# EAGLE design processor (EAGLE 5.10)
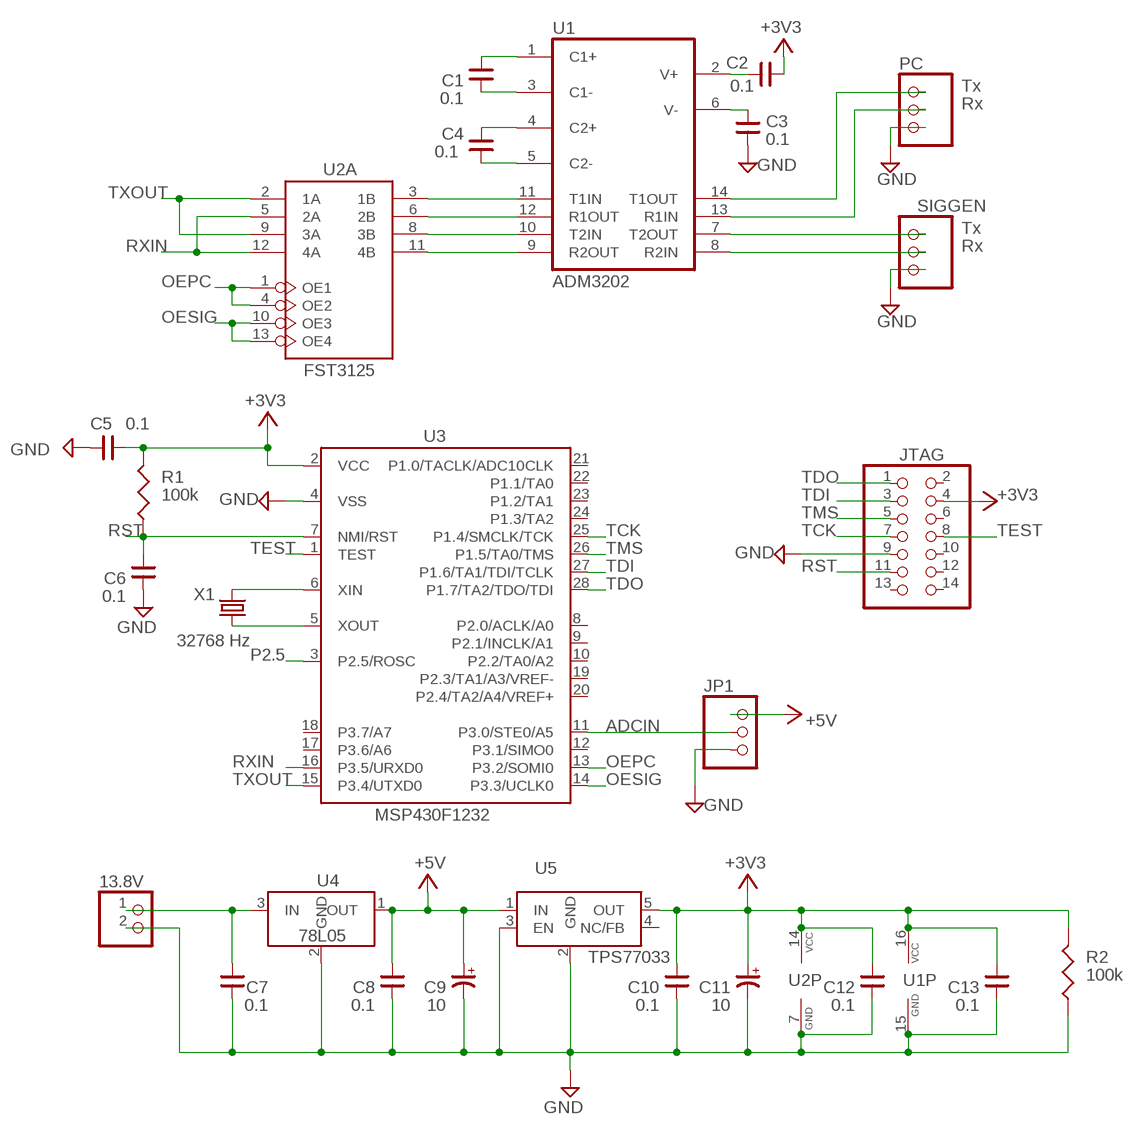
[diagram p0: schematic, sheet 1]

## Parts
13.8V  HIROSE-1X2C  [HIROSE-1X2]
C1  0.1  CAP-NPDC  [805C]
C2  0.1  CAP-NPDC  [805C]
C3  0.1  CAP-NPDC  [805C]
C4  0.1  CAP-NPDC  [805C]
C5  0.1  CAP-NPDC  [805C]
C6  0.1  CAP-NPDC  [805C]
C7  0.1  CAP-NPDC  [805C]
C8  0.1  CAP-NPDC  [805C]
C9  10  CAP-PH  [BC45196H-B]
C10  0.1  CAP-NPDC  [805C]
C11  10  CAP-PH  [BC45196H-B]
C12  0.1  CAP-NPDC  [805C]
C13  0.1  CAP-NPDC  [805C]
JP1  PINHD-1X3A  [1X03A]
JTAG  PINHD-2X7  [2X7]
PC  pc  PINHD-1X3A  [1X03A]
R1  100k  RESISTORC  [805C]
R2  100k  RESISTORC  [805C]
SIGGEN  PINHD-1X3A  [1X03A]
U1  ADM3202  ADM3202A  [SOIC16T]
U2  FST3125  [SO14]
U3  MSP430F1232  [SO-28(DW)]
U4  78L05  VOLTAGE-REGULATOR-FIXEDC  [SOT89]
U5  TPS77033  VOLTAGE-REGULATOR-3  [SOT23-5]
X1  32768 Hz  XTAL  [WATCH-CRYSTAL]

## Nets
13.8V: 13.8V.1 C7.2 U4.3(IN)
+3V3: C2.1 C5.2 C10.2 C11.+ C12.2 C13.2 JTAG.4 R1.2 R2.2 U1.16(VCC) U2.14(P:VCC) U3.2(VCC) U5.5(OUT)
+5V: C8.2 C9.+ JP1.1 U4.1(OUT) U5.1(IN)
ADCIN: JP1.2 U3.11(P3.0/STE0/A5)
GND: 13.8V.2 C3.1 C5.1 C6.1 C7.1 C8.1 C9.- C10.1 C11.- C12.1 C13.1 JP1.3 JTAG.9 PC.1 R2.1 SIGGEN.1 U1.15(GND) U2.7(P:GND) U3.4(VSS) U4.2(GND) U5.2(GND) U5.3(EN)
N$2: U1.11(T1IN) U2.3(A:1B)
N$3: U3.6(XIN) X1.P$2
N$4: U1.12(R1OUT) U2.6(A:2B)
N$8: U3.5(XOUT) X1.P$1
N$9: C2.2 U1.2(V+)
N$10: C1.2 U1.1(C1+)
N$11: C1.1 U1.3(C1-)
N$12: C4.1 U1.4(C2+)
N$13: C4.2 U1.5(C2-)
N$14: C3.2 U1.6(V-)
OEPC: U2.1(A:OE1) U2.4(A:OE2) U3.13(P3.2/SOMI0)
OESIG: U2.10(A:OE3) U2.13(A:OE4) U3.14(P3.3/UCLK0)
P2.5: U3.3(P2.5/ROSC)
PRX: PC.2 U1.13(R1IN)
PTX: PC.3 U1.14(T1OUT)
R2OUT: U1.9(R2OUT) U2.11(A:4B)
RST: C6.2 JTAG.11 R1.1 U3.7(NMI/RST)
RXIN: U2.5(A:2A) U2.12(A:4A) U3.16(P3.5/URXD0)
SRX: SIGGEN.2 U1.8(R2IN)
STX: SIGGEN.3 U1.7(T2OUT)
T2IN: U1.10(T2IN) U2.8(A:3B)
TCK: JTAG.7 U3.25(P1.4/SMCLK/TCK)
TDI: JTAG.3 U3.27(P1.6/TA1/TDI/TCLK)
TDO: JTAG.1 U3.28(P1.7/TA2/TDO/TDI)
TEST: JTAG.8 U3.1(TEST)
TMS: JTAG.5 U3.26(P1.5/TA0/TMS)
TXOUT: U2.2(A:1A) U2.9(A:3A) U3.15(P3.4/UTXD0)
Unconnected: JTAG.2 JTAG.6 JTAG.10 JTAG.12 JTAG.13 JTAG.14 U3.8(P2.0/ACLK/A0) U3.9(P2.1/INCLK/A1) U3.10(P2.2/TA0/A2) U3.12(P3.1/SIMO0) U3.17(P3.6/A6) U3.18(P3.7/A7) U3.19(P2.3/TA1/A3/VREF-) U3.20(P2.4/TA2/A4/VREF+) U3.21(P1.0/TACLK/ADC10CLK) U3.22(P1.1/TA0) U3.23(P1.2/TA1) U3.24(P1.3/TA2) U5.4(NC/FB)

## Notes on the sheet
- Tx
- Rx
- TXOUT
- Tx
- RXIN | Rx
- OEPC
- OESIG
- TDO
- TDI
- TMS
- RST | TCK | TCK | TEST
- TEST | TMS
- TDI | RST
- TDO
- P2.5
- ADCIN
- RXIN | OEPC
- TXOUT | OESIG

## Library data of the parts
13.8V = agarConn:HIROSE-1X2: Hirose DF3-2S-2C, 2 mm pin spacing.
C1-C8 C10 C12 C13 = agar:CAP-NP: Non-polarized capacitor
C9 C11 = agar:CAP-P: Polarized capacitor
JP1 PC SIGGEN = agarConn:PINHD-1X3
JTAG = agarConn:PINHD-2X7
R1 R2 = agar:RESISTOR
U1 = agarDigital:ADM3202: 3.3V dual RS-232 line driver/receiver
U2 = agarDigital:FST3125: 4-Bit Bus Switch
U3 = agarDigital:MSP430F1232
U4 = agarVoltageReg:VOLTAGE-REGULATOR-FIXED: 78xx, 78Lxx. No tRestrict, bRestrict
U5 = agarVoltageReg:VOLTAGE-REGULATOR-3: Voltage regulator with enable. ~ TPS770XX
X1 = agarDigital:XTAL: CRYSTAL

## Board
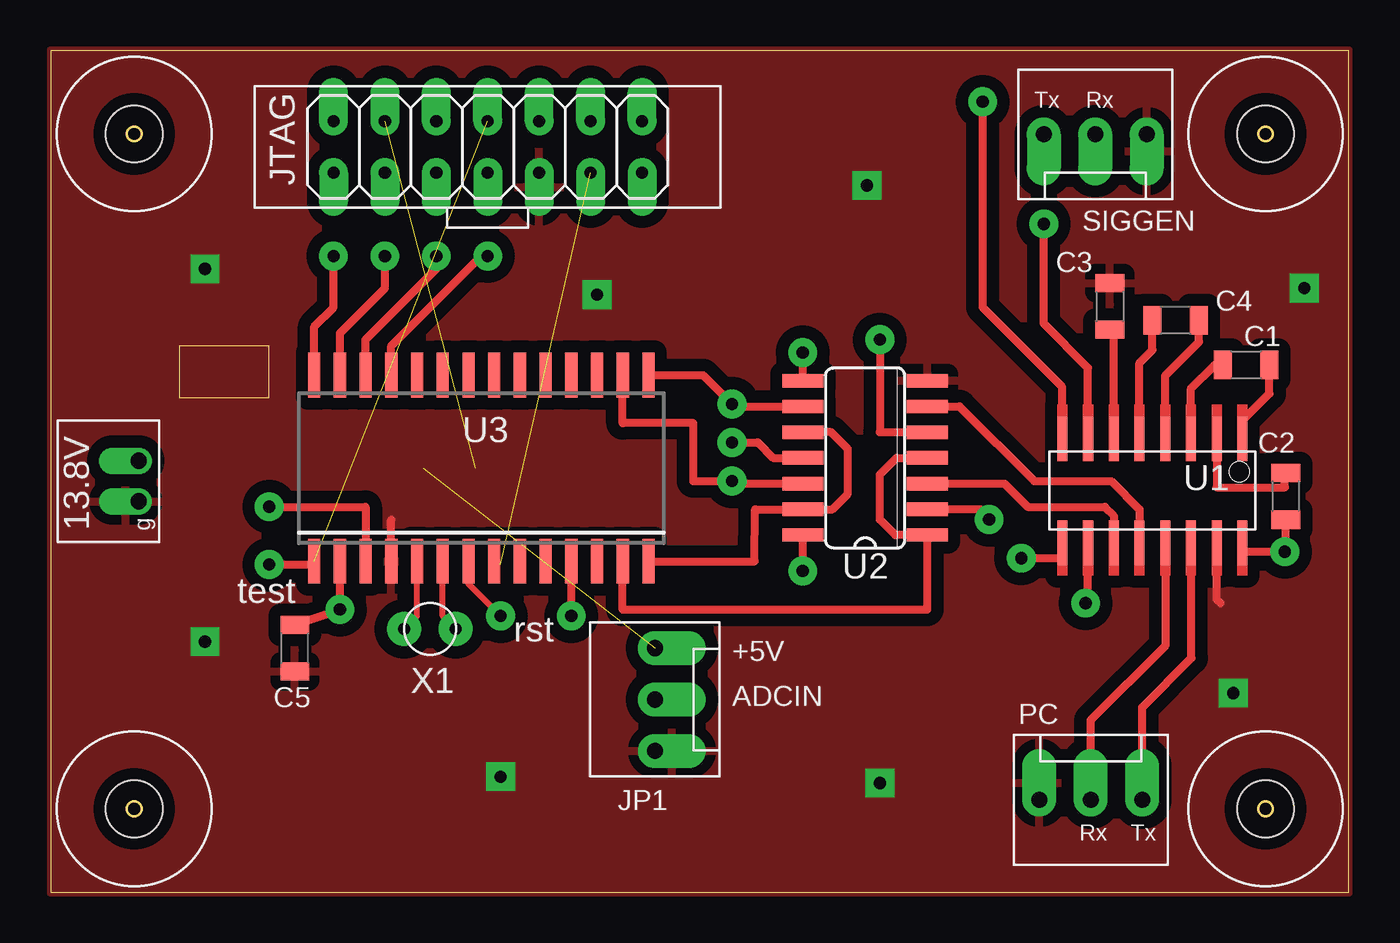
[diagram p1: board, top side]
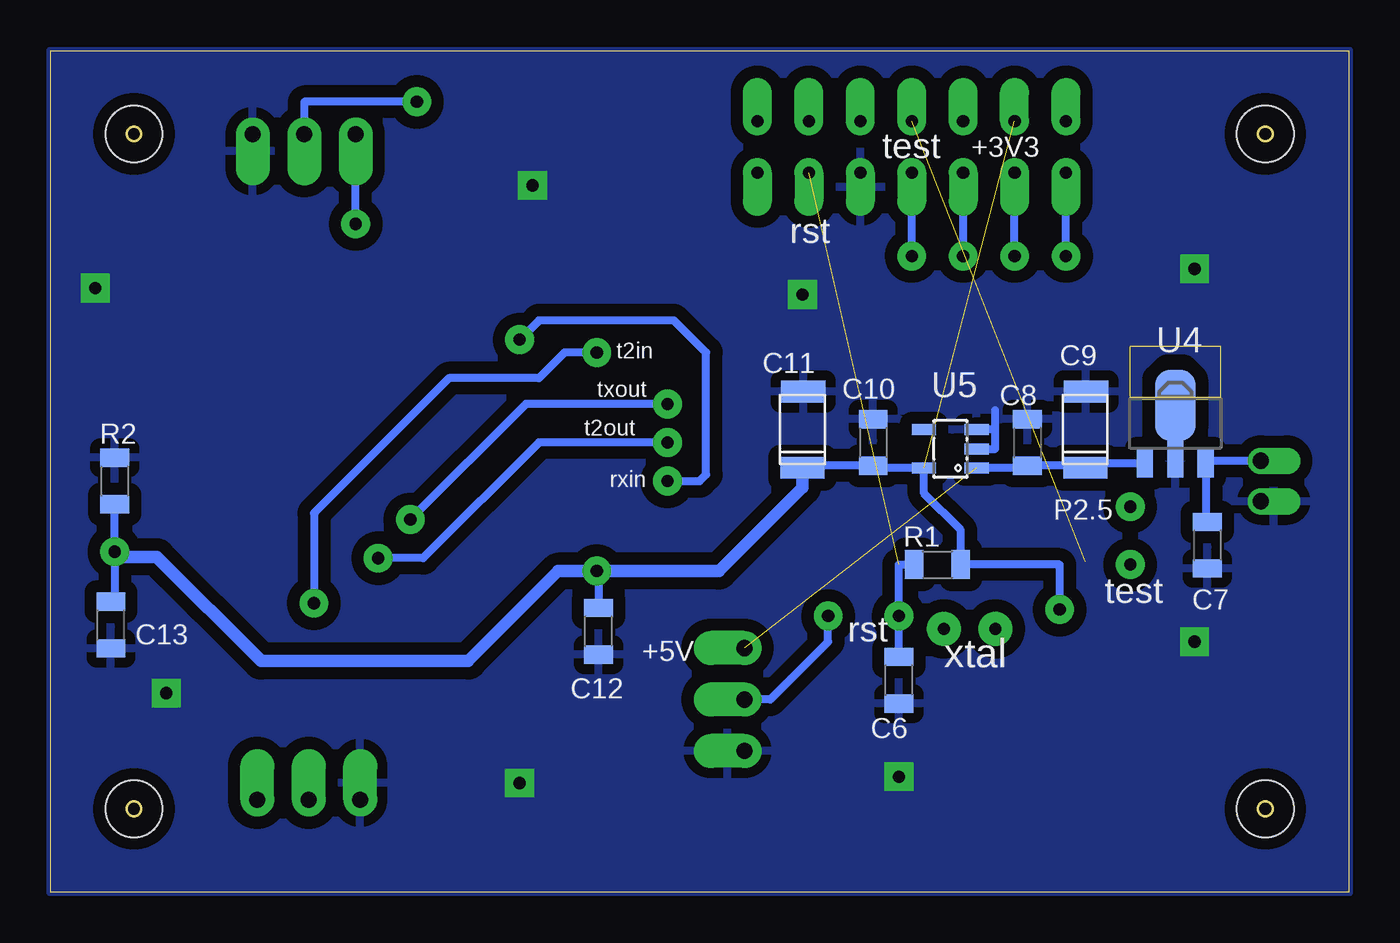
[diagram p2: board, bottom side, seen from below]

Size 64.12 x 41.58 mm. Coordinates in mm from the lower left corner, seen from the top.
Outline: 0,0 64.12,0 64.12,41.58 0,41.58 0,0
Copper layers (1*16): Top 0.035mm / dielectric 1.5mm / Bottom 0.035mm
Design rules "default *": minimum track width 10mil, minimum drill 24mil, track to track 8mil, track to pad 8mil, pad to pad 8mil, via to via 8mil, smd to smd 8mil, copper to edge 0mil, drill to drill 8mil, minimum pad ring 10mil, minimum via ring 8mil, stop-mask expansion 4mil, vias tented up to drill 0mil, thermal gap 20mil
bRestrict: area 17.8,21.9 to 18.4,22.9
Milling: area 6.3,24.4 to 10.8,27

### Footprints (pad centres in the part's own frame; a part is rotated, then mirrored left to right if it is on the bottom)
HIROSE-1X2 = drill 0.8 offset: 1 -1,1.5; 2 1,1.5
805C = smd 0.9 x 1.422: 1 -1.15,0; 2 1.15,0
BC45196H-B = smd 1.067 x 2.184: + -1.883,0; - 1.883,-0.038
1X03A = drill 0.8 pad 1.676 offset: 1 0,2.54; 2 0,0; 3 0,-2.54
2X7 = drill 0.6 pad 1.422 offset: 1 -6.35,-1.27; 2 -6.35,1.27; 3 -3.81,-1.27; 4 -3.81,1.27; 5 -1.27,-1.27; 6 -1.27,1.27; 7 1.27,-1.27; 8 1.27,1.27; 9 3.81,-1.27; 10 3.81,1.27; 11 6.35,-1.27; 12 6.35,1.27; 13 8.89,-1.27; 14 8.89,1.27
SOIC16T = smd 0.5 x 2.2: 1 -4.106,-2.523; 2 -2.836,-2.523; 3 -1.566,-2.523; 4 -0.296,-2.523; 5 0.974,-2.523; 6 2.244,-2.523; 7 3.514,-2.523; 8 4.784,-2.523; 9 4.784,2.619; 10 3.514,2.619; 11 2.244,2.619; 12 0.974,2.619; 13 -0.296,2.619; 14 -1.566,2.619; 15 -2.836,2.619; 16 -4.106,2.619; 17 -2.836,2.619; 18 -2.836,2.619
SO14 = smd 0.66 x 2.032: 1 -3.81,-3.073; 2 -2.54,-3.073; 3 -1.27,-3.073; 4 0,-3.073; 5 1.27,-3.073; 6 2.54,-3.073; 7 3.81,-3.073; 8 3.81,3.073; 9 2.54,3.073; 10 1.27,3.073; 11 0,3.073; 12 -1.27,3.073; 13 -2.54,3.073; 14 -3.81,3.073
SO-28(DW) = smd 0.6 x 2.2: 1 -8.255,-4.6; 2 -6.985,-4.6; 3 -5.715,-4.6; 4 -4.445,-4.6; 5 -3.175,-4.6; 6 -1.905,-4.6; 7 -0.635,-4.6; 8 0.635,-4.6; 9 1.905,-4.6; 10 3.175,-4.6; 11 4.445,-4.6; 12 5.715,-4.6; 13 6.985,-4.6; 14 8.255,-4.6; 15 8.255,4.6; 16 6.985,4.6; 17 5.715,4.6; 18 4.445,4.6; 19 3.175,4.6; 20 1.905,4.6; 21 0.635,4.6; 22 -0.635,4.6; 23 -1.905,4.6; 24 -3.175,4.6; 25 -4.445,4.6; 26 -5.715,4.6; 27 -6.985,4.6; 28 -8.255,4.6
SOT89 = smd 0.8 x 1.4: 1 -1.499,-1.981; 3 1.499,-1.981 | smd 0.8 x 1.9: 2 0,-1.727 | smd 2 x 3.5: 4 0,0.889
SOT23-5 = smd 0.55 x 1.2: 1 -0.95,-1.3; 2 0,-1.3; 3 0.95,-1.3; 4 0.95,1.3; 5 -0.95,1.3
MOUNTING-HOLE-PLAIN = hole 2.8: 0,0
WATCH-CRYSTAL = drill 0.6 pad 1.676 round: P$1 -1.27,0; P$2 1.27,0

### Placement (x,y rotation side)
13.8V  2.86,20.32 270 top
C1  59.05,26.06 0 top
C2  61.01,19.56 90 top
C3  52.32,28.95 270 top
C4  55.56,28.26 180 top
C5  12.06,12.07 90 top
C6  22.22,10.48 90 bottom
C7  6.98,17.15 90 bottom
C8  15.88,22.23 270 bottom
C9  13.02,22.86 90 bottom
C10  23.5,22.23 270 bottom
C11  26.99,22.86 90 bottom
C12  37.06,12.9 90 bottom
C13  61.14,13.21 90 bottom
JP1  29.85,9.53 0 top
JTAG  20.32,36.83 0 top
PC  51.38,4.57 90 top
R1  20.32,16.19 0 bottom
R2  60.96,20.32 270 bottom
SIGGEN  51.6,37.45 270 top
U1  54.76,19.9 180 top
U2  40.23,21.46 90 top
U3  21.27,20.96 0 top
U4  8.57,23.18 0 bottom
U5  19.68,21.91 90 bottom
U$1  [MOUNTING-HOLE-PLAIN]  4.13,37.46 0 top
U$2  [MOUNTING-HOLE-PLAIN]  4.13,4.13 0 top
U$3  [MOUNTING-HOLE-PLAIN]  60.01,4.13 0 top
U$4  [MOUNTING-HOLE-PLAIN]  60.01,37.46 0 top
X1  18.73,13.02 0 top

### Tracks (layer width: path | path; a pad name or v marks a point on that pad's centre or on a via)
13.8V
  Bottom 0.406: C7.2 7.07,18.29 7.07,20.64 U4.3 7.07,21.32 13.8V.1
+3V3  (via drill 0.6 pad 1.42)  (1 unrouted)
  Top 0.406: C5.2 v14.29,13.97 U3.2 | v37.15,15.87 37.15,17.64 U2.14 | U1.16 58.86,16.83 v60.96,16.83 61.01,16.83 C2.1
  Bottom 0.406: v14.29,13.97 14.29,14.6 14.29,16.19 R1.2 19.17,17.9 20.99,19.72 U5.5 23.38,20.96 C10.2 | C13.2 60.96,14.36 v60.96,16.83 | C10.2 23.5,20.92 | C10.2 26.99,21.07 C11.+ | v37.15,15.87 37.06,15.87 C12.2 | 60.71,16.58 v60.96,16.83 | v60.96,16.83 R2.2
  Bottom 0.61: C11.+ 26.99,20 31.11,15.87 v37.15,15.87 39.05,15.87 43.5,11.43 53.73,11.43 58.88,16.58 60.71,16.58
+5V  (1 unrouted)
  Bottom 0.406: U4.1 13.02,21.2 C9.+ 13.02,21.07 C8.2 15.99,20.96 U5.1
ADCIN  (via drill 0.6 pad 1.42)
  Top 0.406: v25.72,13.65 U3.11
  Bottom 0.406: JP1.2 28.58,9.53 25.72,12.38 v25.72,13.65
GND  (via drill 0.6 pad 1.42)
  Top 0.406: U3.4 16.83,18.42 | U1.15 57.59,14.48 57.78,14.29
  Bottom 0.406: U5.2 17.46,21.91 17.46,22.86 | 17.46,22.86 U5.3 | 17.46,22.86 17.46,23.81
  other vias: 40.96,5.4 61.91,29.85 26.99,29.53 22.22,5.72 58.42,9.84 40.32,34.93 7.62,30.8 7.62,12.38
  pour Top (isolate 0.61): 0,0 64.12,0 64.12,41.58 0,41.58
  pour Bottom (isolate 0.61): 0,0 64.12,0 64.12,41.58 0,41.58
N$2
  Top 0.406: U2.3 47.12,20.19 48.26,19.05 52.07,19.05 52.51,18.61 U1.11
N$3
  Top 0.305: X1.P$2 19.37,13.65 U3.6
N$4
  Top 0.406: U1.12 53.78,18.93 52.39,20.32 48.58,20.32 44.9,24 U2.6
N$8
  Top 0.305: X1.P$1 18.1,13.65 U3.5
N$9
  Top 0.406: U1.2 57.59,20 60.96,20 60.96,20.71 C2.2
N$10
  Top 0.406: U1.1 58.86,23.3 60.2,24.64 C1.2
N$11
  Top 0.406: U1.3 56.32,24.89 57.47,26.04 57.87,26.04 C1.1
N$12
  Top 0.406: U1.4 55.05,25.52 56.72,27.19 C4.1
N$13
  Top 0.406: U1.5 53.78,26.16 54.42,26.79 C4.2
N$14
  Top 0.406: U1.6 52.51,27.6 C3.2
OEPC
  Top 0.406: U2.4 41.78,21.46 40.96,20.64 40.96,18.42 41.72,17.65 U2.1 43.31,13.97 28.26,13.97 U3.13
OESIG
  Top 0.406: U2.10 38.54,22.73 39.37,21.91 39.37,19.68 38.61,18.92 U2.13 34.8,18.92 34.77,16.36 U3.14
P2.5  (via drill 0.6 pad 1.42)
  Top 0.406: v10.79,19.05 15.56,19.05 U3.3
PRX
  Top 0.406: PC.2 51.37,8.51 55.07,12.21 55.07,17.26 U1.13
PTX
  Top 0.406: PC.3 53.92,9.15 56.34,11.57 56.34,17.26 U1.14
R2OUT  (via drill 0.6 pad 1.42)
  Top 0.406: U2.11 35.69,21.46 34.93,22.22 v33.65,22.22 | v47.94,16.51 49.97,16.51 U1.9
  Bottom 0.406: v47.94,16.51 45.72,16.51 40,22.22 v33.65,22.22
RST  (via drill 0.6 pad 1.42)  (1 unrouted)
  Top 0.305: U3.7 20.64,15.24 v22.22,13.65
  Bottom 0.406: R1.1 22.22,16.19 v22.22,13.65 C6.2
RXIN  (via drill 0.6 pad 1.42)
  Top 0.406: U2.12 33.65,20.19 v33.65,20.32 31.75,20.32 31.75,23.18 28.26,23.18 U3.16 | U2.5 40.96,22.73 v40.96,27.3
  Bottom 0.406: v40.96,27.3 40,28.26 33.34,28.26 31.75,26.67 31.75,20.64 32.07,20.32 v33.65,20.32
SRX  (via drill 0.6 pad 1.42)
  Top 0.406: U1.8 49.97,24.96 46.04,28.89 v46.04,39.05
  Bottom 0.406: v46.04,39.05 51.6,39.05 SIGGEN.2
STX  (via drill 0.6 pad 1.42)
  Top 0.406: v49.05,33.02 49.05,28.1 51.24,25.91 U1.7
  Bottom 0.406: SIGGEN.3 v49.05,33.02
T2IN  (via drill 0.6 pad 1.42)
  Top 0.406: U2.8 37.16,26.66 v37.15,26.67 | v51.12,14.29 51.24,14.29 U1.10
  Bottom 0.406: v37.15,26.67 38.73,26.67 40,25.4 44.45,25.4 51.12,18.73 v51.12,14.29
TCK  (via drill 0.6 pad 1.42)
  Top 0.406: v21.59,31.43 21.27,31.43 16.83,26.99 U3.25
  Bottom 0.406: v21.59,31.43 JTAG.7
TDI  (via drill 0.6 pad 1.42)
  Top 0.406: v16.51,31.43 16.51,29.85 14.29,27.62 U3.27
  Bottom 0.406: v16.51,31.43 JTAG.3
TDO  (via drill 0.6 pad 1.42)
  Top 0.406: v13.97,31.43 13.97,28.89 13.02,27.94 U3.28
  Bottom 0.406: v13.97,31.43 JTAG.1
TEST  (via drill 0.6 pad 1.42)  (1 unrouted)
  Top 0.406: v10.79,16.19 13.02,16.19 U3.1
TMS  (via drill 0.6 pad 1.42)
  Top 0.406: v19.05,31.43 19.05,30.8 15.56,27.3 U3.26
  Bottom 0.406: v19.05,31.43 JTAG.5
TXOUT  (via drill 0.6 pad 1.42)
  Top 0.305: U3.15 29.53,26.38
  Top 0.406: U2.9 33.78,24 v33.65,24.13 32.23,25.55 U3.15 | U2.2 45.91,18.92 v46.36,18.42
  Bottom 0.406: v33.65,24.13 40.64,24.13 v46.36,18.42

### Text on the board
tNames: Tx | Rx | test | rst | +5V | ADCIN | Rx | Tx
bNames: +3V3 | test | rst | t2in | txout | t2out | rxin | P2.5 | test | rst | xtal | +5V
